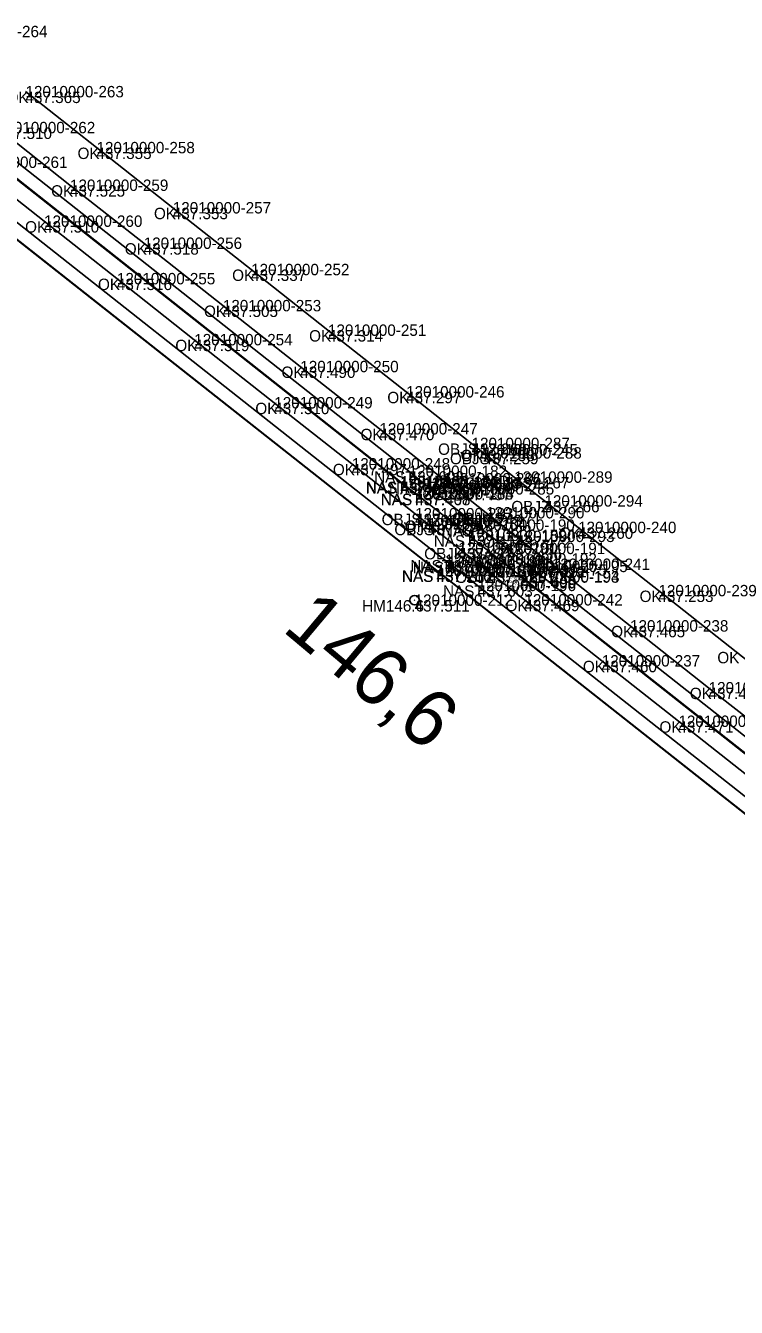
# Model space of a CAD drawing. Extents: x -653665 to -652742, y -1166300 to -1165487.
# Drawn here: x -653305 to -653230.2, y -1165894.6 to -1165759.7 of the extents above; entities that cross this region are included whole.
import ezdxf

# ---------------------------------------------------------------- set-up
doc = ezdxf.new("R2010")
doc.units = 0
for name, color, linetype in [('Vrstva 1', 7, 'Continuous'), ('Vrstva 14', 7, 'Continuous'), ('Vrstva 60', 7, 'Continuous'), ('Vrstva 61', 7, 'Continuous'), ('Vrstva 62', 7, 'Continuous'), ('Vrstva 7', 7, 'Continuous')]:
    doc.layers.add(name, color=color, linetype=linetype)

msp = doc.modelspace()

# ---------------------------------------------------------------- linework, layer by layer
at = {"layer": 'Vrstva 1'}
for points in [[(-653222.41, -1165831.79), (-653230.27, -1165825.59), (-653238.45, -1165819.14), (-653246.91, -1165812.49), (-653250.45, -1165809.7), (-653253.63, -1165807.19), (-653256.87, -1165804.65), (-653257.27, -1165804.32), (-653258.12, -1165803.65), (-653265, -1165798.22), (-653273.23, -1165791.73), (-653281.32, -1165785.35), (-653289.56, -1165778.85), (-653297.59, -1165772.52), (-653305.06, -1165766.63)], [(-653225.2, -1165835.63), (-653233.17, -1165829.36), (-653241.44, -1165822.85), (-653249.68, -1165816.37), (-653253.42, -1165813.43), (-653256.59, -1165810.94), (-653259.77, -1165808.43), (-653260.22, -1165808.08), (-653261.13, -1165807.37), (-653267.82, -1165802.11), (-653276.14, -1165795.56), (-653284.29, -1165789.15), (-653292.62, -1165782.58), (-653300.38, -1165776.48), (-653308.07, -1165770.41)], [(-653227.85, -1165839.58), (-653236.35, -1165832.89), (-653244.41, -1165826.53), (-653252.56, -1165820.11), (-653256.35, -1165817.13), (-653259.51, -1165814.65), (-653262.72, -1165812.11), (-653263.17, -1165811.76), (-653264.06, -1165811.05), (-653270.72, -1165805.8), (-653278.88, -1165799.37), (-653287.3, -1165792.74), (-653295.44, -1165786.31), (-653303.11, -1165780.26), (-653310.99, -1165774.05)]]:
    msp.add_lwpolyline(points, dxfattribs=at)
at = {"layer": 'Vrstva 14'}
for p, q in [((-653258.45, -1165813.32), (-653257.6, -1165812.25)), ((-653255.28, -1165815.81), (-653254.4, -1165814.7))]:
    msp.add_line(p, q, dxfattribs=at)
for points in [[(-653264.73, -1165806.58), (-653318.56, -1165764.12), (-653319.39, -1165763.51), (-653320.24, -1165764.59), (-653320.26, -1165764.64), (-653319.44, -1165765.26), (-653265.62, -1165807.73), (-653264.04, -1165808.96), (-653264.01, -1165808.93), (-653258.45, -1165813.32), (-653255.28, -1165815.81), (-653252.89, -1165817.67), (-653252.91, -1165817.71), (-653185.94, -1165870.54), (-653160.89, -1165890.22), (-653160.13, -1165890.87), (-653160.09, -1165890.83), (-653159.23, -1165889.74), (-653160.03, -1165889.1), (-653185.12, -1165869.34), (-653252.03, -1165816.59), (-653254.4, -1165814.7), (-653257.6, -1165812.25), (-653263.18, -1165807.82)], [(-653323.43, -1165768.49), (-653323.42, -1165768.47), (-653322.55, -1165767.36), (-653321.77, -1165767.96), (-653260.92, -1165815.93), (-653260.66, -1165816.11), (-653257.48, -1165818.59), (-653188.19, -1165873.27), (-653163.42, -1165892.82), (-653162.59, -1165893.47), (-653163.54, -1165894.55), (-653163.55, -1165894.57), (-653164.32, -1165893.92), (-653188.97, -1165874.49), (-653261.81, -1165817.03), (-653322.62, -1165769.1)]]:
    msp.add_lwpolyline(points, close=True, dxfattribs=at)
for points in [[(-653320.24, -1165764.59), (-653319.41, -1165765.19), (-653265.58, -1165807.68), (-653264.01, -1165808.93)], [(-653323.42, -1165768.47), (-653322.59, -1165769.06), (-653261.78, -1165817.01), (-653188.99, -1165874.41), (-653164.29, -1165893.89), (-653163.54, -1165894.55)], [(-653252.89, -1165817.67), (-653185.98, -1165870.43), (-653160.87, -1165890.18), (-653160.09, -1165890.83)]]:
    msp.add_lwpolyline(points, dxfattribs=at)
at = {"layer": 'Vrstva 60'}
for p, q in [((-653297.59, -1165772.52), (-653297.59, -1165772.52)), ((-653300.38, -1165776.48), (-653300.38, -1165776.48)), ((-653289.56, -1165778.85), (-653289.56, -1165778.85)), ((-653303.11, -1165780.26), (-653303.11, -1165780.26)), ((-653292.62, -1165782.58), (-653292.62, -1165782.58)), ((-653295.44, -1165786.31), (-653295.44, -1165786.31)), ((-653281.32, -1165785.35), (-653281.32, -1165785.35)), ((-653284.29, -1165789.15), (-653284.29, -1165789.15)), ((-653273.23, -1165791.73), (-653273.23, -1165791.73)), ((-653287.3, -1165792.74), (-653287.3, -1165792.74)), ((-653276.14, -1165795.56), (-653276.14, -1165795.56)), ((-653265, -1165798.22), (-653265, -1165798.22)), ((-653278.88, -1165799.37), (-653278.88, -1165799.37)), ((-653267.82, -1165802.11), (-653267.82, -1165802.11)), ((-653258.12, -1165803.65), (-653258.12, -1165803.65)), ((-653257.27, -1165804.32), (-653257.27, -1165804.32)), ((-653256.87, -1165804.65), (-653256.87, -1165804.65)), ((-653270.72, -1165805.8), (-653270.72, -1165805.8)), ((-653264.73, -1165806.58), (-653264.73, -1165806.58)), ((-653265.62, -1165807.73), (-653265.62, -1165807.73)), ((-653265.58, -1165807.68), (-653265.58, -1165807.68)), ((-653263.18, -1165807.82), (-653263.18, -1165807.82)), ((-653261.13, -1165807.37), (-653261.13, -1165807.37)), ((-653260.22, -1165808.08), (-653260.22, -1165808.08)), ((-653253.63, -1165807.19), (-653253.63, -1165807.19)), ((-653264.04, -1165808.96), (-653264.04, -1165808.96)), ((-653264.01, -1165808.93), (-653264.01, -1165808.93)), ((-653259.77, -1165808.43), (-653259.77, -1165808.43)), ((-653250.45, -1165809.7), (-653250.45, -1165809.7)), ((-653264.06, -1165811.05), (-653264.06, -1165811.05)), ((-653263.17, -1165811.76), (-653263.17, -1165811.76)), ((-653262.72, -1165812.11), (-653262.72, -1165812.11)), ((-653257.6, -1165812.25), (-653257.6, -1165812.25)), ((-653256.59, -1165810.94), (-653256.59, -1165810.94)), ((-653258.45, -1165813.32), (-653258.45, -1165813.32)), ((-653253.42, -1165813.43), (-653253.42, -1165813.43)), ((-653246.91, -1165812.49), (-653246.91, -1165812.49)), ((-653259.51, -1165814.65), (-653259.51, -1165814.65)), ((-653254.4, -1165814.7), (-653254.4, -1165814.7)), ((-653260.92, -1165815.93), (-653260.92, -1165815.93)), ((-653260.66, -1165816.11), (-653260.66, -1165816.11)), ((-653255.28, -1165815.81), (-653255.28, -1165815.81)), ((-653261.81, -1165817.03), (-653261.81, -1165817.03)), ((-653261.78, -1165817.01), (-653261.78, -1165817.01)), ((-653256.35, -1165817.13), (-653256.35, -1165817.13)), ((-653252.03, -1165816.59), (-653252.03, -1165816.59)), ((-653249.68, -1165816.37), (-653249.68, -1165816.37)), ((-653257.48, -1165818.59), (-653257.48, -1165818.59)), ((-653252.91, -1165817.71), (-653252.91, -1165817.71)), ((-653252.89, -1165817.67), (-653252.89, -1165817.67)), ((-653264.11, -1165820.14), (-653264.11, -1165820.14)), ((-653252.56, -1165820.11), (-653252.56, -1165820.11)), ((-653238.45, -1165819.14), (-653238.45, -1165819.14)), ((-653241.44, -1165822.85), (-653241.44, -1165822.85)), ((-653230.27, -1165825.59), (-653230.27, -1165825.59)), ((-653244.41, -1165826.53), (-653244.41, -1165826.53)), ((-653233.17, -1165829.36), (-653233.17, -1165829.36)), ((-653236.35, -1165832.89), (-653236.35, -1165832.89))]:
    msp.add_line(p, q, dxfattribs=at)
at = {"layer": 'Vrstva 7'}
msp.add_line((-653264.15, -1165820.1), (-653264.07, -1165820.17), dxfattribs=at)
msp.add_circle((-653264.11, -1165820.14), 0.5, dxfattribs=at)

# ---------------------------------------------------------------- texts
at = {"layer": 'Vrstva 60'}
for s, p in [('12010000-264', (-653313.1, -1165760.9)), ('12010000-263', (-653305.06, -1165767.23)), ('12010000-262', (-653308.07, -1165771.01)), ('12010000-258', (-653297.59, -1165773.12)), ('12010000-261', (-653310.99, -1165774.66)), ('12010000-259', (-653300.38, -1165777.08)), ('12010000-257', (-653289.56, -1165779.45)), ('12010000-260', (-653303.11, -1165780.86)), ('12010000-256', (-653292.62, -1165783.18)), ('12010000-252', (-653281.32, -1165785.95)), ('12010000-255', (-653295.44, -1165786.91)), ('12010000-253', (-653284.29, -1165789.75)), ('12010000-251', (-653273.23, -1165792.33)), ('12010000-254', (-653287.3, -1165793.33)), ('12010000-250', (-653276.14, -1165796.16)), ('12010000-249', (-653278.88, -1165799.97)), ('12010000-246', (-653265, -1165798.82)), ('12010000-247', (-653267.82, -1165802.71)), ('12010000-287', (-653258.12, -1165804.25)), ('12010000-245', (-653257.27, -1165804.92)), ('12010000-288', (-653256.87, -1165805.25)), ('12010000-248', (-653270.72, -1165806.4)), ('12010000-182', (-653264.73, -1165807.18)), ('12010000-286', (-653261.13, -1165807.97)), ('12010000-289', (-653253.63, -1165807.79)), ('12010000-180', (-653265.62, -1165808.33)), ('12010000-181', (-653265.58, -1165808.28)), ('12010000-183', (-653263.18, -1165808.42)), ('12010000-244', (-653260.22, -1165808.68)), ('12010000-285', (-653259.77, -1165809.03)), ('12010000-185', (-653264.04, -1165809.56)), ('12010000-184', (-653264.01, -1165809.53)), ('12010000-294', (-653250.45, -1165810.3)), ('12010000-283', (-653264.06, -1165811.65)), ('12010000-290', (-653256.59, -1165811.54)), ('12010000-243', (-653263.17, -1165812.36)), ('12010000-284', (-653262.72, -1165812.71)), ('12010000-190', (-653257.6, -1165812.84)), ('12010000-240', (-653246.91, -1165813.09)), ('12010000-189', (-653258.45, -1165813.92)), ('12010000-293', (-653253.42, -1165814.03)), ('12010000-291', (-653259.51, -1165815.25)), ('12010000-191', (-653254.4, -1165815.3)), ('12010000-188', (-653260.92, -1165816.53)), ('12010000-199', (-653260.66, -1165816.71)), ('12010000-192', (-653255.28, -1165816.41)), ('12010000-195', (-653252.03, -1165817.19)), ('12010000-241', (-653249.68, -1165816.97)), ('12010000-186', (-653261.81, -1165817.63)), ('12010000-187', (-653261.78, -1165817.61)), ('12010000-292', (-653256.35, -1165817.73)), ('12010000-193', (-653252.91, -1165818.31)), ('12010000-194', (-653252.89, -1165818.27)), ('12010000-196', (-653257.48, -1165819.19)), ('12010000-239', (-653238.45, -1165819.74)), ('12010000-212', (-653264.11, -1165820.74)), ('12010000-242', (-653252.56, -1165820.71)), ('12010000-238', (-653241.44, -1165823.45)), ('12010000-237', (-653244.41, -1165827.13)), ('12010000-235', (-653233.17, -1165829.96)), ('12010000-236', (-653236.35, -1165833.49))]:
    msp.add_text(s, height=1.2, dxfattribs=at).set_placement(p)
at = {"layer": 'Vrstva 61'}
for s, p in [('437.365', (-653305.06, -1165767.83)), ('437.510', (-653308.07, -1165771.61)), ('437.355', (-653297.59, -1165773.72)), ('437.525', (-653300.38, -1165777.68)), ('437.353', (-653289.56, -1165780.05)), ('437.510', (-653303.11, -1165781.46)), ('437.518', (-653292.62, -1165783.78)), ('437.516', (-653295.44, -1165787.51)), ('437.337', (-653281.32, -1165786.55)), ('437.505', (-653284.29, -1165790.34)), ('437.314', (-653273.23, -1165792.93)), ('437.519', (-653287.3, -1165793.94)), ('437.490', (-653276.14, -1165796.76)), ('437.297', (-653265, -1165799.42)), ('437.510', (-653278.88, -1165800.57)), ('437.470', (-653267.82, -1165803.31)), ('437.269', (-653258.12, -1165804.85)), ('437.258', (-653257.27, -1165805.52)), ('437.259', (-653256.87, -1165805.84)), ('437.497', (-653270.72, -1165807)), ('437.603', (-653264.73, -1165807.78)), ('437.401', (-653265.62, -1165808.93)), ('437.719', (-653265.58, -1165808.88)), ('437.466', (-653263.18, -1165809.02)), ('437.472', (-653261.13, -1165808.57)), ('437.467', (-653260.22, -1165809.28)), ('437.267', (-653253.63, -1165808.39)), ('437.468', (-653264.04, -1165810.16)), ('437.497', (-653264.01, -1165810.13)), ('437.467', (-653259.77, -1165809.63)), ('437.266', (-653250.45, -1165810.9)), ('437.482', (-653264.06, -1165812.25)), ('437.475', (-653263.17, -1165812.96)), ('437.477', (-653262.72, -1165813.31)), ('437.422', (-653257.6, -1165813.45)), ('437.471', (-653256.59, -1165812.14)), ('437.457', (-653258.45, -1165814.52)), ('437.472', (-653253.42, -1165814.63)), ('437.260', (-653246.91, -1165813.69)), ('437.477', (-653259.51, -1165815.85)), ('437.436', (-653254.4, -1165815.9)), ('437.614', (-653260.92, -1165817.13)), ('437.619', (-653260.66, -1165817.31)), ('437.460', (-653255.28, -1165817.01)), ('437.266', (-653261.81, -1165818.23)), ('437.710', (-653261.78, -1165818.21)), ('437.471', (-653256.35, -1165818.33)), ('437.690', (-653252.89, -1165818.87)), ('437.623', (-653252.03, -1165817.79)), ('437.475', (-653249.68, -1165817.57)), ('437.603', (-653257.48, -1165819.79)), ('437.499', (-653252.91, -1165818.91)), ('437.511', (-653264.11, -1165821.34)), ('437.469', (-653252.56, -1165821.31)), ('437.253', (-653238.45, -1165820.34)), ('437.465', (-653241.44, -1165824.05)), ('437.460', (-653244.41, -1165827.73)), ('437.464', (-653233.17, -1165830.56)), ('437.471', (-653236.35, -1165834.09))]:
    msp.add_text(s, height=1.2, dxfattribs=at).set_placement(p)
at = {"layer": 'Vrstva 62'}
for s, p in [('OK', (-653307.05, -1165767.83)), ('OK', (-653299.58, -1165773.72)), ('OK', (-653302.36, -1165777.68)), ('OK', (-653291.54, -1165780.05)), ('OK', (-653305.1, -1165781.46)), ('OK', (-653294.61, -1165783.78)), ('OK', (-653297.43, -1165787.51)), ('OK', (-653283.31, -1165786.55)), ('OK', (-653286.27, -1165790.34)), ('OK', (-653275.21, -1165792.93)), ('OK', (-653289.29, -1165793.94)), ('OK', (-653278.12, -1165796.76)), ('OK', (-653266.98, -1165799.42)), ('OK', (-653280.87, -1165800.57)), ('OK', (-653269.8, -1165803.31)), ('OBJS', (-653261.64, -1165804.85)), ('OBJS', (-653260.39, -1165805.84)), ('OK', (-653259.26, -1165805.52)), ('OK', (-653272.71, -1165807)), ('NAST', (-653268.37, -1165807.78)), ('NAST', (-653269.26, -1165808.93)), ('NAST', (-653269.22, -1165808.88)), ('NAST', (-653266.81, -1165809.02)), ('OBJS', (-653264.65, -1165808.57)), ('OK', (-653262.2, -1165809.28)), ('OBJK', (-653257.22, -1165808.39)), ('NAST', (-653267.68, -1165810.16)), ('NAST', (-653267.65, -1165810.13)), ('OBJS', (-653263.29, -1165809.63)), ('OBJZ', (-653253.93, -1165810.9)), ('OBJS', (-653267.58, -1165812.25)), ('OBJS', (-653266.24, -1165813.31)), ('OK', (-653265.15, -1165812.96)), ('NAST', (-653261.24, -1165813.45)), ('OBJK', (-653260.18, -1165812.14)), ('NAST', (-653262.09, -1165814.52)), ('OBJZ', (-653256.9, -1165814.63)), ('OK', (-653248.89, -1165813.69)), ('OBJK', (-653263.1, -1165815.85)), ('NAST', (-653258.04, -1165815.9)), ('NAST', (-653264.56, -1165817.13)), ('NAST', (-653264.3, -1165817.31)), ('NAST', (-653258.92, -1165817.01)), ('NAST', (-653265.45, -1165818.23)), ('NAST', (-653265.42, -1165818.21)), ('OBJZ', (-653259.83, -1165818.33)), ('NAST', (-653256.53, -1165818.87)), ('NAST', (-653255.67, -1165817.79)), ('OK', (-653251.66, -1165817.57)), ('NAST', (-653261.12, -1165819.79)), ('NAST', (-653256.55, -1165818.91)), ('HM146.6', (-653269.63, -1165821.34)), ('OK', (-653254.54, -1165821.31)), ('OK', (-653240.43, -1165820.34)), ('OK', (-653243.42, -1165824.05)), ('OK', (-653232.25, -1165826.79)), ('OK', (-653246.4, -1165827.73)), ('OK', (-653235.15, -1165830.56)), ('OK', (-653238.34, -1165834.09))]:
    msp.add_text(s, height=1.2, dxfattribs=at).set_placement(p)
at = {"layer": 'Vrstva 7'}
msp.add_text('146,6', height=6, rotation=320, dxfattribs=at).set_placement((-653278.16, -1165823.3))

doc.saveas('drawing.dxf')
